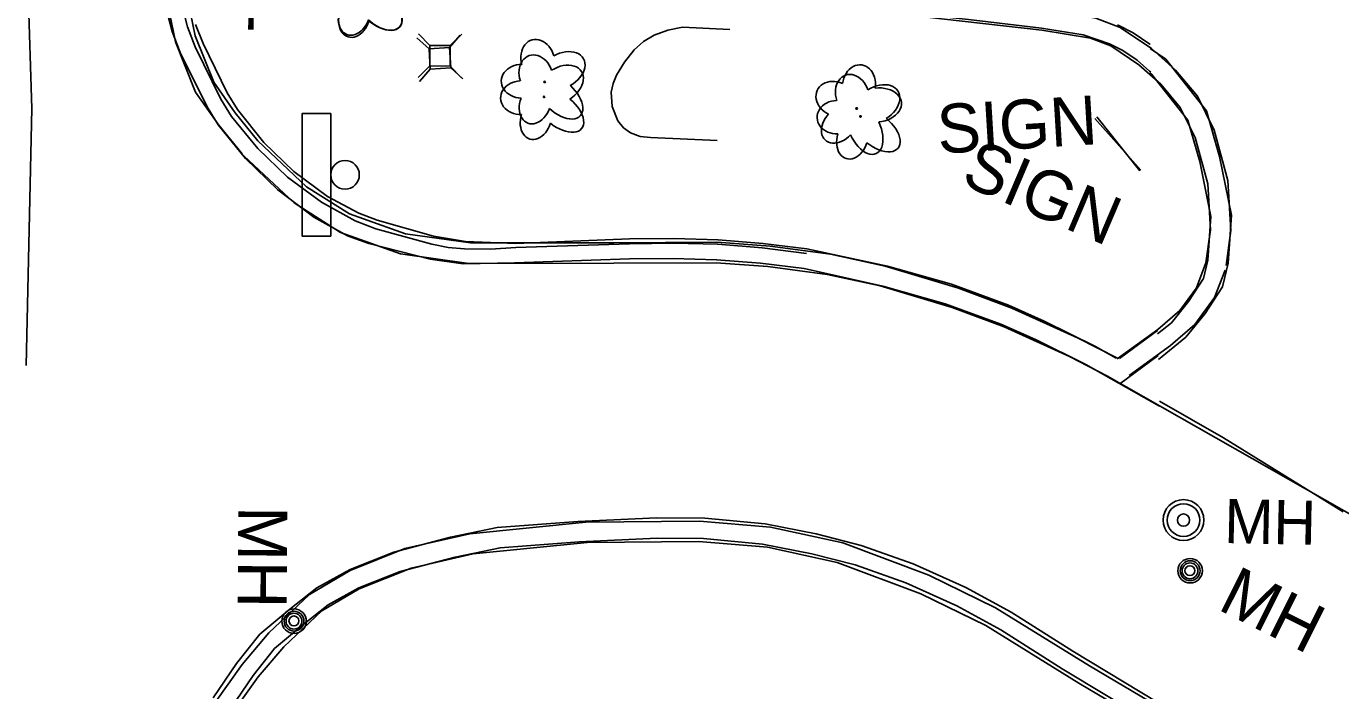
# Model space of a CAD drawing. Extents: x 588843 to 2552415, y 180129 to 269402.
# Drawn here: x 594769.1 to 594930, y 184364.2 to 184445.5 of the extents above; entities that cross this region are included whole.
import ezdxf

# ---------------------------------------------------------------- set-up
doc = ezdxf.new("R2010")
doc.units = 0
for name, color, linetype in [('Default', 7, 'Continuous'), ('E_DRN_Text', 7, 'Continuous'), ('E_DWY', 7, 'Continuous'), ('E_LAND_Vegetation', 7, 'Continuous'), ('E_MISCPROP_Planter', 7, 'Continuous'), ('E_RDWY_C_and_G', 7, 'Continuous'), ('E_RDWY_PavtEdge', 7, 'Continuous'), ('E_SGN', 7, 'Continuous'), ('E_SGN_Text', 7, 'Continuous'), ('E_UTL_AG_Bold', 7, 'Continuous'), ('E_UTL_MH', 7, 'Continuous'), ('E_UTL_MH_Text', 7, 'Continuous'), ('E_UTL_SAN', 7, 'Continuous'), ('Level 11', 7, 'Continuous'), ('Level 17', 7, 'Continuous')]:
    doc.layers.add(name, color=color, linetype=linetype)

# ---------------------------------------------------------------- blocks, each defined once
blk = doc.blocks.new('MHO')
at = {"layer": 'Default'}
for centre, radius in [((0.08, -0.12), 3), ((0.08, -0.12), 2.43), ((0.07, -0.15), 1.94), ((0.02, -0.16), 1.21)]:
    blk.add_circle(centre, radius, dxfattribs=at)
blk = doc.blocks.new('MHT')
at = {"layer": 'E_UTL_MH_Text'}
blk.add_text('MH', height=12, dxfattribs=at).set_placement((-9.81, -6))
blk = doc.blocks.new('INLT_57')
at = {"layer": 'E_DRN_Text'}
blk.add_text('INL', height=12, dxfattribs=at).set_placement((-11.03, -6))
blk = doc.blocks.new('PED')
at = {"layer": 'Default'}
for p, q in [((-2.5, 2.5), (-5.33, 5.33)), ((2.5, 2.5), (5.33, 5.33)), ((-2.5, -2.5), (-5.33, -5.33)), ((2.5, -2.5), (5.33, -5.33))]:
    blk.add_line(p, q, dxfattribs=at)
blk.add_lwpolyline([(-2.5, -2.5), (2.5, -2.5), (2.5, 2.5), (-2.5, 2.5)], close=True, dxfattribs=at)
blk = doc.blocks.new('SIGN')
at = {"layer": 'Default'}
blk.add_text('SIGN', height=12, dxfattribs=at).set_placement((-18.55, -6))
blk = doc.blocks.new('DTRE')
at = {"layer": 'Default'}
blk.add_circle((-0.18, 0), 0.183, dxfattribs=at)
for centre, major_axis, ratio in [((-1.87, 5.32), (1.36, -4.98), 0.782863), ((4.06, 2.74), (-5.27, -2.93), 0.691916), ((-5.87, 0.15), (4.93, -0.12), 0.832022), ((3.54, -3.71), (-5.01, 4.58), 0.560249), ((-2.49, -5.24), (1.8, 4.86), 0.716896)]:
    blk.add_ellipse(centre, major_axis=major_axis, ratio=ratio, start_param=1.570796, end_param=4.712389, dxfattribs=at)
blk = doc.blocks.new('SGN_1')
at = {"layer": 'Default'}
blk.add_lwpolyline([(-3.5, -15), (-10.5, -15), (-10.5, 15), (-3.5, 15)], close=True, dxfattribs=at)
blk.add_circle((0, 0), 3.5, dxfattribs=at)
blk = doc.blocks.new('DTRE_1_1')
at = {"layer": 'Default'}
blk.add_circle((-0.18, 0), 0.183, dxfattribs=at)
for centre, major_axis, ratio in [((-1.87, 5.32), (1.36, -4.98), 0.782863), ((4.06, 2.74), (-5.27, -2.93), 0.691916), ((-5.87, 0.15), (4.93, -0.12), 0.832022), ((3.54, -3.71), (-5.01, 4.58), 0.560249), ((-2.49, -5.24), (1.8, 4.86), 0.716896)]:
    blk.add_ellipse(centre, major_axis=major_axis, ratio=ratio, start_param=1.570796, end_param=4.712389, dxfattribs=at)
blk = doc.blocks.new('MH')
at = {"layer": 'E_UTL_MH'}
for radius in [5, 4, 1.5]:
    blk.add_circle((0, 0), radius, dxfattribs=at)
blk.add_text('MH', height=10.8, dxfattribs=at).set_placement((10, -5.4))
blk = doc.blocks.new('MHO_3')
at = {"layer": 'E_UTL_MH'}
for centre, radius in [((0.3, -0.4), 9.84), ((0.3, -0.4), 7.98), ((0.2, -0.5), 6.35), ((0.1, -0.5), 3.97)]:
    blk.add_circle(centre, radius, dxfattribs=at)
blk = doc.blocks.new('MHT_3')
at = {"layer": 'E_UTL_MH_Text'}
blk.add_text('MH', height=39.37, dxfattribs=at).set_placement((-32.2, -19.7))
blk = doc.blocks.new('PED_3')
at = {"layer": 'E_UTL_AG_Bold'}
for p, q in [((-8.2, 8.2), (-17.5, 17.5)), ((8.2, 8.2), (17.5, 17.5)), ((-8.2, -8.2), (-17.5, -17.5)), ((8.2, -8.2), (17.5, -17.5))]:
    blk.add_line(p, q, dxfattribs=at)
blk.add_lwpolyline([(-8.2, -8.2), (8.2, -8.2), (8.2, 8.2), (-8.2, 8.2)], close=True, dxfattribs=at)
blk = doc.blocks.new('SIGN_3')
at = {"layer": 'E_SGN'}
blk.add_text('SIGN', height=39.37, dxfattribs=at).set_placement((-56.1, -19.7))
blk = doc.blocks.new('DTRE_4')
at = {"layer": 'E_LAND_Vegetation'}
blk.add_circle((-0.6, 0), 0.601, dxfattribs=at)
for centre, major_axis, ratio in [((-6.1, 17.5), (4.5, -16.3), 0.782863), ((13.3, 9), (-17.3, -9.6), 0.691916), ((-19.3, 0.5), (16.2, -0.4), 0.832022), ((11.6, -12.2), (-16.4, 15), 0.560249), ((-8.2, -17.2), (5.9, 15.9), 0.716896)]:
    blk.add_ellipse(centre, major_axis=major_axis, ratio=ratio, start_param=1.570796, end_param=4.712389, dxfattribs=at)

msp = doc.modelspace()

# ---------------------------------------------------------------- linework, layer by layer
at = {"layer": 'E_DWY'}
for points in [[(594869.45, 184450.2), (594893.72, 184447.47), (594899.98, 184446.43), (594902.99, 184445.32), (594906.81, 184442.74), (594909.76, 184440.1), (594912.44, 184436.9), (594914.49, 184432.73), (594916.17, 184426.58), (594916.54, 184420.45), (594915.96, 184416.17)], [(594855.26, 184449.34), (594873.7, 184447.42), (594884.41, 184446.28), (594893.35, 184445.22), (594898.45, 184444.41), (594901.66, 184443.32), (594903.31, 184442.49), (594905.07, 184441.3), (594906.58, 184439.96)], [(594869.17, 184447.72), (594893.38, 184444.99), (594899.34, 184444), (594901.84, 184443.08), (594905.27, 184440.76), (594907.96, 184438.36), (594910.33, 184435.53), (594912.14, 184431.84), (594913.69, 184426.17), (594914.03, 184420.55), (594913.48, 184416.5)], [(594902.63, 184445.63), (594904.58, 184444.65), (594906.59, 184443.28)], [(594906.59, 184443.28), (594906.6, 184443.28), (594906.63, 184443.25)], [(594906.58, 184439.96), (594906.72, 184439.84)], [(594913.48, 184416.5), (594912.31, 184413.46), (594910.28, 184410.66), (594907.57, 184408.37), (594902.59, 184404.76)], [(594915.81, 184415.6), (594914.52, 184412.26), (594912.12, 184408.95), (594909.12, 184406.4), (594904.06, 184402.74)], [(594907.55, 184408.22), (594902.91, 184404.8)], [(594907.63, 184405.17), (594902.95, 184401.71)]]:
    msp.add_lwpolyline(points, dxfattribs=at)
at = {"layer": 'E_MISCPROP_Planter'}
msp.add_lwpolyline([(594855.17, 184445.05), (594849.4, 184445.34), (594847.61, 184445), (594845.91, 184444.37), (594845.91, 184444.37), (594844.6, 184443.59), (594843.48, 184442.56), (594843.48, 184442.56), (594842.3, 184441.08), (594841.31, 184439.48), (594841.31, 184439.48), (594840.89, 184438.47), (594840.68, 184437.39), (594840.68, 184437.39), (594840.8, 184435.65), (594840.8, 184435.65), (594841.49, 184433.9), (594841.49, 184433.9), (594842.16, 184433.05), (594843.03, 184432.43), (594843.03, 184432.43), (594844.22, 184431.99), (594845.47, 184431.85), (594845.47, 184431.85), (594853.64, 184431.49)], dxfattribs=at)
at = {"layer": 'E_RDWY_C_and_G'}
for points in [[(594784.28, 184494.37), (594786.78, 184494.45), (594787.88, 184463.06), (594788.86, 184448.44), (594789.74, 184444.29), (594792.01, 184438.6), (594794.61, 184434.87), (594797.41, 184431.43)], [(594784.28, 184494.37), (594785.39, 184462.93), (594786.38, 184448.1), (594787.34, 184443.57), (594789.79, 184437.4), (594792.62, 184433.37), (594795.47, 184429.85)], [(594864.28, 184415.8), (594858.93, 184416.46), (594853.57, 184416.88), (594853.57, 184416.88), (594848.25, 184417.06), (594842.92, 184417), (594842.92, 184417), (594828.82, 184416.49), (594822.53, 184416.4), (594822.53, 184416.4), (594818.51, 184416.94), (594818.51, 184416.94), (594811.01, 184418.86), (594811.01, 184418.86), (594808.37, 184419.83), (594808.37, 184419.83), (594804.26, 184422.1), (594804.26, 184422.1), (594799.84, 184425.44), (594799.84, 184425.44), (594795.9, 184429.28), (594795.9, 184429.28), (594792.56, 184433.41), (594792.56, 184433.41), (594791.21, 184435.6), (594791.21, 184435.6), (594787.91, 184442.25), (594787.91, 184442.25), (594786.91, 184444.81), (594786.23, 184447.48)], [(594864.57, 184417.66), (594859.15, 184418.36), (594853.7, 184418.78), (594853.7, 184418.78), (594848.29, 184418.93), (594842.89, 184418.82), (594842.89, 184418.82), (594829.01, 184418.38), (594825.87, 184418.19), (594822.72, 184418.21), (594822.72, 184418.21), (594820.7, 184418.39), (594818.7, 184418.78), (594818.7, 184418.78), (594811.85, 184420.67), (594811.85, 184420.67), (594809.34, 184421.64), (594809.34, 184421.64), (594805.18, 184423.94), (594805.18, 184423.94), (594801.05, 184426.99), (594801.05, 184426.99), (594797.39, 184430.49), (594797.39, 184430.49), (594794.19, 184434.42), (594794.19, 184434.42), (594792.88, 184436.54), (594792.88, 184436.54), (594789.73, 184442.96), (594789.73, 184442.96), (594788.79, 184445.38), (594788.15, 184447.9)], [(594864.63, 184418.21), (594859.21, 184418.88), (594853.76, 184419.31), (594853.76, 184419.31), (594848.33, 184419.49), (594842.9, 184419.44), (594842.9, 184419.44), (594829, 184418.88), (594822.83, 184419.11), (594822.83, 184419.11), (594818.9, 184419.79), (594818.9, 184419.79), (594812.03, 184421.73), (594812.03, 184421.73), (594809.75, 184422.58), (594809.75, 184422.58), (594805.95, 184424.63), (594805.95, 184424.63), (594801.8, 184427.7), (594801.8, 184427.7), (594798.13, 184431.24), (594798.13, 184431.24), (594794.91, 184435.26), (594794.91, 184435.26), (594793.67, 184437.3), (594793.67, 184437.3), (594790.71, 184443.33), (594790.71, 184443.33), (594789.79, 184445.68)], [(594797.41, 184431.43), (594803.38, 184425.83), (594808.62, 184422.49), (594815.49, 184420.07), (594823.42, 184418.94), (594840.98, 184418.97)], [(594795.7, 184429.61), (594801.84, 184423.84), (594807.51, 184420.23), (594814.89, 184417.63), (594823.25, 184416.44), (594840.98, 184416.47)], [(594840.98, 184418.97), (594853.61, 184419.02), (594860.12, 184418.53), (594867.52, 184417.56), (594874.22, 184416.1), (594883.2, 184413.42), (594889.72, 184410.98), (594897.84, 184407.28), (594902.55, 184404.9), (594902.68, 184404.82)], [(594902.48, 184404.85), (594899.96, 184406.28), (594893.66, 184409.39), (594889.31, 184411.31), (594882.33, 184413.89), (594874.48, 184416.11), (594864.63, 184418.21)], [(594840.99, 184416.47), (594853.52, 184416.52), (594859.86, 184416.05), (594867.1, 184415.1), (594873.59, 184413.68), (594882.4, 184411.05), (594888.77, 184408.67), (594896.76, 184405.03), (594901.36, 184402.7), (594932.46, 184384.96), (594940.08, 184381.5)], [(594907.79, 184398.96), (594898.79, 184404.07), (594892.6, 184407.12), (594888.37, 184408.99), (594881.55, 184411.51), (594873.9, 184413.67), (594864.28, 184415.8)], [(594907.57, 184362.7), (594897.2, 184368.97), (594889.63, 184373.77), (594884.08, 184376.79), (594877.65, 184379.67), (594871.27, 184381.93), (594865.76, 184383.34), (594859.53, 184384.56), (594852.11, 184385.25), (594846.24, 184385.31), (594836.58, 184384.85), (594826.72, 184384.12), (594821.01, 184382.93), (594814.05, 184381.12), (594808.69, 184379), (594804.62, 184376.75), (594801.31, 184374.13), (594797.65, 184371.08), (594794.81, 184367.48), (594791.95, 184363.27)], [(594786.22, 184343.19), (594786.88, 184348.37), (594787.84, 184352.98), (594789.45, 184357.33), (594792.04, 184362.54), (594795.47, 184367.36), (594798.75, 184371.25), (594803.75, 184375.92), (594808.71, 184378.87), (594815.42, 184381.56), (594823.37, 184383.36), (594837.57, 184384.79), (594851.47, 184384.89), (594860.16, 184384.18), (594869.02, 184382.24), (594879.55, 184378.28), (594887.72, 184374.3), (594899.21, 184367.2), (594911.84, 184359.72), (594921.62, 184354.99)], [(594788.7, 184342.87), (594789.35, 184347.96), (594790.25, 184352.29), (594791.75, 184356.34), (594794.19, 184361.26), (594797.44, 184365.83), (594800.57, 184369.52), (594805.26, 184373.91), (594809.82, 184376.62), (594816.17, 184379.16), (594823.77, 184380.89), (594837.71, 184382.29), (594851.38, 184382.39), (594859.79, 184381.7), (594868.31, 184379.84), (594878.56, 184375.99), (594886.51, 184372.11), (594897.91, 184365.06), (594910.66, 184357.51), (594920.53, 184352.74)], [(594906.33, 184360.53), (594895.88, 184366.84), (594888.36, 184371.62), (594882.97, 184374.55), (594876.72, 184377.34), (594870.54, 184379.54), (594865.21, 184380.9), (594859.17, 184382.08), (594851.98, 184382.76), (594846.29, 184382.81), (594836.73, 184382.36), (594827.06, 184381.64), (594821.58, 184380.49), (594814.82, 184378.74), (594809.77, 184376.74), (594806.01, 184374.66), (594802.89, 184372.19), (594799.45, 184369.33), (594796.82, 184366), (594794.07, 184361.94)]]:
    msp.add_lwpolyline(points, dxfattribs=at)
at = {"layer": 'E_RDWY_PavtEdge'}
msp.add_lwpolyline([(594769.06, 184403.96), (594769.74, 184435.38), (594769.3, 184449.63)], dxfattribs=at)
at = {"layer": 'E_SGN'}
msp.add_line((594899.87, 184434.18), (594905.51, 184427.86), dxfattribs=at)
msp.add_lwpolyline([(594905.4, 184427.76), (594900.12, 184434.39)], dxfattribs=at)
at = {"layer": 'Level 11'}
msp.add_lwpolyline([(594907.81, 184399.6), (594915.61, 184395.1), (594930.27, 184386.02)], dxfattribs=at)
at = {"layer": 'Level 17'}
for points in [[(594906.63, 184442.73), (594908.58, 184441.43), (594913.54, 184435.12), (594915.14, 184429.52), (594916.59, 184422.35), (594916.18, 184416.45), (594915.51, 184413.59), (594913.38, 184410.29), (594911.01, 184407.4), (594907.66, 184404.68)], [(594906.59, 184439.75), (594906.86, 184439.57), (594911.27, 184433.96), (594912.71, 184428.93), (594914.07, 184422.19), (594913.7, 184416.83), (594913.17, 184414.58), (594911.36, 184411.76), (594909.24, 184409.18), (594907.56, 184407.83)]]:
    msp.add_lwpolyline(points, dxfattribs=at)

# ---------------------------------------------------------------- block references
at = {"layer": 'E_DRN_Text', "xscale": 0.5000000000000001, "yscale": 0.5, "rotation": -90.36283032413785}
msp.add_blockref('INLT_57', (594799.26, 184451.74), dxfattribs=at)
at = {"layer": 'E_LAND_Vegetation'}
for name, p, xscale, yscale, rotation in [('DTRE_4', (594810.31, 184449.32), 0.15240030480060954, 0.15240030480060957, 3.4338469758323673), ('DTRE_4', (594832.54, 184436.82), 0.15240030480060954, 0.15240030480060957, 3.4338469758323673), ('DTRE', (594870.8, 184435.36), 0.5, 0.5, -23.084058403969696), ('DTRE_4', (594871.28, 184434.43), 0.15240030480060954, 0.15240030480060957, 3.4338469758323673)]:
    msp.add_blockref(name, p, dxfattribs=dict(at, xscale=xscale, yscale=yscale, rotation=rotation))
at = {"layer": 'E_LAND_Vegetation', "xscale": 0.5, "yscale": 0.5}
for p in [(594810.46, 184449.5), (594832.61, 184438.65)]:
    msp.add_blockref('DTRE_1_1', p, dxfattribs=at)
at = {"layer": 'E_SGN', "xscale": 0.5, "yscale": 0.5}
msp.add_blockref('SGN_1', (594808.08, 184427.28), dxfattribs=at)
at = {"layer": 'E_SGN_Text'}
for name, p, xscale, yscale, rotation in [('SIGN_3', (594889.09, 184433.37), 0.15240030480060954, 0.15240030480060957, 3.4338469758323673), ('SIGN', (594893, 184425.35), 0.5, 0.5, -23.084058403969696)]:
    msp.add_blockref(name, p, dxfattribs=dict(at, xscale=xscale, yscale=yscale, rotation=rotation))
at = {"layer": 'E_UTL_AG_Bold'}
for name, p, xscale, yscale, rotation in [('PED_3', (594819.69, 184441.53), 0.15240030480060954, 0.15240030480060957, 3.4338469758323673), ('PED', (594819.71, 184441.85), 0.5000000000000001, 0.5, -90.36283032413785)]:
    msp.add_blockref(name, p, dxfattribs=dict(at, xscale=xscale, yscale=yscale, rotation=rotation))
at = {"layer": 'E_UTL_MH'}
for name, p, xscale, yscale, rotation in [('MHO_3', (594911.53, 184378.91), 0.15240030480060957, 0.1524003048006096, -26.610656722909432), ('MHO', (594801.9, 184372.7), 0.5000000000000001, 0.5, -90.36283032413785)]:
    msp.add_blockref(name, p, dxfattribs=dict(at, xscale=xscale, yscale=yscale, rotation=rotation))
at = {"layer": 'E_UTL_MH_Text'}
for name, p, xscale, yscale, rotation in [('MHT', (594797.98, 184381.82), 0.5000000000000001, 0.5, -90.36283032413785), ('MHT_3', (594920.49, 184374.66), 0.15240030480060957, 0.1524003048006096, -26.610656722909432)]:
    msp.add_blockref(name, p, dxfattribs=dict(at, xscale=xscale, yscale=yscale, rotation=rotation))
at = {"layer": 'E_UTL_SAN', "xscale": 0.500001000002, "yscale": 0.5000010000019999, "rotation": -1.2027594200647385}
msp.add_blockref('MH', (594910.73, 184385.03), dxfattribs=at)

doc.saveas('drawing.dxf')
